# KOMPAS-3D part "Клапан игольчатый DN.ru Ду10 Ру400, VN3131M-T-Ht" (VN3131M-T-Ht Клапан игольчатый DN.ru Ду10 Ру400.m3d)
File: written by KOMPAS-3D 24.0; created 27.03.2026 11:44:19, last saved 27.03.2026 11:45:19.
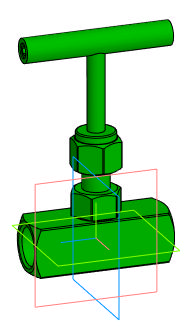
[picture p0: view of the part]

Document properties: Автор: Илья; Полное имя файла: D:\Обмен\Заказы с фриланса\DN.ru\VNxxM-T-Ht Клапан игольчатый DN.ru Ду8-50 Ру400\VN3131M-T-Ht Клапан игольчатый DN.ru Ду8-50 Ру400\DN10\VN3131M-T-Ht Клапан игольчатый DN.ru Ду10 Ру400.m3d

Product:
- Body: Body3  | qty 1
    Масса: 0.224966
- Part/product: Клапан игольчатый DN.ru Ду10 Ру400  | designation VN3131M-T-Ht
    Масса: 0.4
    Раздел спецификации: Прочие изделия
    Примечание: D090-02130

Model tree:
1. Body3  (labels: Body3)

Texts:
  VN3131M-T-Ht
